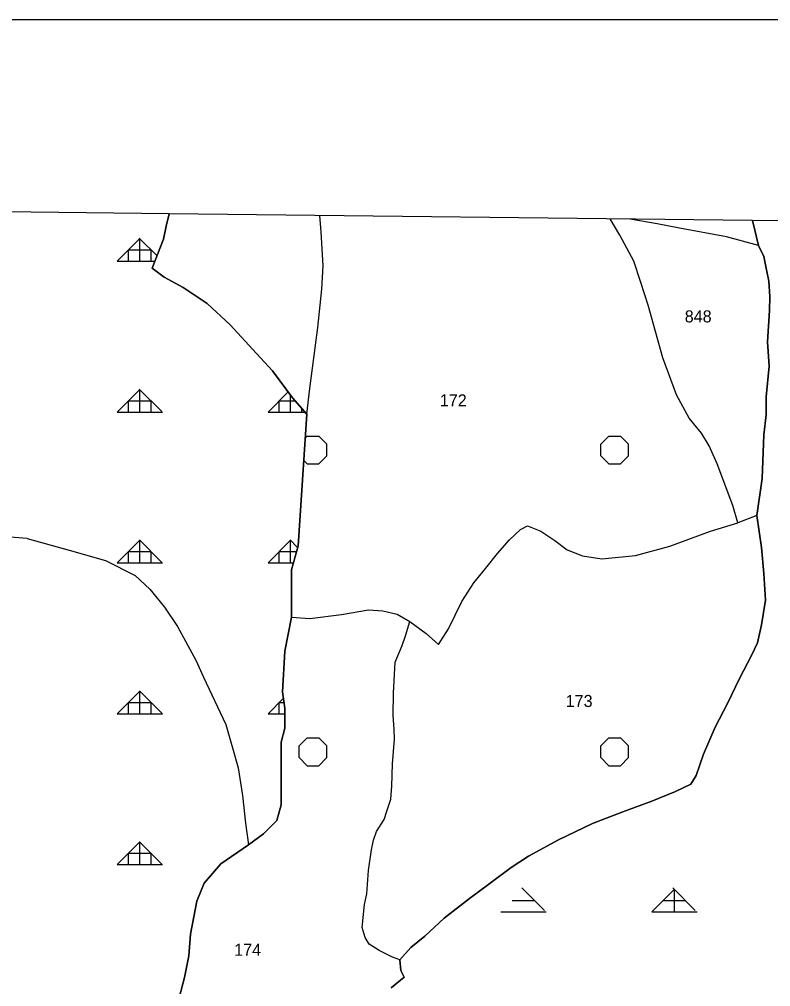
# Model space of a CAD drawing. Extents: x 410727 to 412947, y 4463506 to 4466382.
# Drawn here: x 411945.5 to 412194.6, y 4466061 to 4466381.6 of the extents above; entities that cross this region are included whole.
import ezdxf

# ---------------------------------------------------------------- set-up
doc = ezdxf.new("R2010")
doc.units = 0
for name, color, linetype in [('ADAKENARI', 7, 'Continuous'), ('KDS_PARSEL_NO', 7, 'Continuous'), ('KDS_PL', 7, 'Continuous'), ('LJ_ÇERÇEVE', 7, 'Continuous'), ('PL_AYA_ORMAN', 7, 'Continuous'), ('PL_KA_TARIM_DIGER', 7, 'Continuous'), ('TR_ORMAN', 7, 'Continuous'), ('TR_TARIMALANI', 7, 'Continuous')]:
    doc.layers.add(name, color=color, linetype=linetype)

msp = doc.modelspace()

# ---------------------------------------------------------------- linework, layer by layer
at = {"layer": 'ADAKENARI'}
for p, q in [((411995.18, 4466317.19), (411994.2, 4466313.01)), ((412188.64, 4466314.49), (412188.49, 4466314.92)), ((412190.58, 4466306.63), (412188.64, 4466314.49)), ((411994.2, 4466313.01), (411993.35, 4466308.76)), ((411993.35, 4466308.76), (411989.59, 4466299.17)), ((412192.36, 4466303.06), (412190.58, 4466306.63)), ((412193.19, 4466298.54), (412192.36, 4466303.06)), ((411989.59, 4466299.17), (411993.47, 4466296.14)), ((412194.03, 4466294.85), (412193.19, 4466298.54)), ((411993.47, 4466296.14), (411999.78, 4466292.74)), ((412194.3, 4466289.77), (412194.03, 4466294.85)), ((411999.78, 4466292.74), (412007.79, 4466287.39)), ((412194.23, 4466285.11), (412194.3, 4466289.77)), ((412007.79, 4466287.39), (412015.43, 4466280.35)), ((412193.54, 4466274.67), (412194.23, 4466285.11)), ((412015.43, 4466280.35), (412024.17, 4466270.89)), ((412194.1, 4466266.67), (412193.54, 4466274.67)), ((412024.17, 4466270.89), (412029.39, 4466265.07)), ((412193.12, 4466256.51), (412194.1, 4466266.67)), ((412029.39, 4466265.07), (412036.06, 4466256.21)), ((412036.06, 4466256.21), (412040.79, 4466250.75)), ((412193.12, 4466250.53), (412193.12, 4466256.51)), ((412040.79, 4466250.75), (412037.93, 4466207.15)), ((412040.79, 4466250.75), (412040.79, 4466250.75)), ((412192.29, 4466243.92), (412193.12, 4466250.53)), ((412191.73, 4466229.38), (412192.29, 4466243.92)), ((412189.99, 4466217.14), (412191.73, 4466229.38)), ((412191.58, 4466206.6), (412189.99, 4466217.14)), ((412037.93, 4466207.15), (412035.73, 4466199.13)), ((412192.29, 4466198), (412191.58, 4466206.6)), ((412035.73, 4466199.13), (412035.73, 4466183.47)), ((412192.85, 4466189.11), (412192.29, 4466198)), ((412191.58, 4466180.93), (412192.85, 4466189.11)), ((412035.73, 4466183.47), (412033.48, 4466172.18)), ((412190.17, 4466175), (412191.58, 4466180.93)), ((412188.27, 4466170.77), (412190.17, 4466175)), ((412033.48, 4466172.18), (412032.79, 4466158.71)), ((412184.26, 4466163.15), (412188.27, 4466170.77)), ((412180.24, 4466154.83), (412184.26, 4466163.15)), ((412032.79, 4466158.71), (412033.53, 4466153.32)), ((412176.23, 4466147.07), (412180.24, 4466154.83)), ((412033.53, 4466153.32), (412033.53, 4466146.71)), ((412033.53, 4466146.71), (412032.3, 4466142.05)), ((412172.36, 4466138.06), (412176.23, 4466147.07)), ((412032.3, 4466142.05), (412032.3, 4466137.15)), ((412169.87, 4466131), (412172.36, 4466138.06)), ((412032.3, 4466137.15), (412032.3, 4466133.48)), ((412032.3, 4466133.48), (412032.3, 4466128.58)), ((412032.3, 4466128.58), (412032.3, 4466121.23)), ((412163.09, 4466125.73), (412168.07, 4466128.08)), ((412168.07, 4466128.08), (412169.87, 4466131)), ((412155.21, 4466122.54), (412163.09, 4466125.73)), ((412145.53, 4466118.94), (412155.21, 4466122.54)), ((412032.3, 4466121.23), (412030.84, 4466116.08)), ((412135.57, 4466115.06), (412145.53, 4466118.94)), ((412030.84, 4466116.08), (412026.43, 4466111.67)), ((412124.23, 4466109.65), (412135.57, 4466115.06)), ((412026.43, 4466111.67), (412021.48, 4466107.99)), ((412114.27, 4466104.25), (412124.23, 4466109.65)), ((412021.48, 4466107.99), (412012.31, 4466101.72)), ((412108.6, 4466100.5), (412114.27, 4466104.25)), ((412012.31, 4466101.72), (412006.79, 4466095.33)), ((412101.13, 4466094.96), (412108.6, 4466100.5)), ((412006.79, 4466095.33), (412004.32, 4466089.32)), ((412094.76, 4466090.25), (412101.13, 4466094.96)), ((412086.33, 4466083.74), (412094.76, 4466090.25)), ((412004.32, 4466089.32), (412002.22, 4466078.45)), ((412079.96, 4466077.78), (412086.33, 4466083.74)), ((412002.22, 4466078.45), (412001.67, 4466071.26)), ((412075.26, 4466074.03), (412079.96, 4466077.78)), ((412071.66, 4466069.88), (412075.26, 4466074.03)), ((412001.67, 4466071.26), (412000.29, 4466064.06)), ((412071.94, 4466066.41), (412071.66, 4466069.88)), ((412000.29, 4466064.06), (411997.25, 4466052.69)), ((412068.76, 4466060.59), (412073.05, 4466064.19)), ((412073.05, 4466064.19), (412071.94, 4466066.41))]:
    msp.add_line(p, q, dxfattribs=at)
at = {"layer": 'KDS_PL'}
for p, q in [((411995.18, 4466317.19), (411994.2, 4466313.01)), ((412045.53, 4466311.18), (412045.13, 4466316.6)), ((412144.59, 4466310.02), (412141.35, 4466315.48)), ((412156.99, 4466313.79), (412148.01, 4466315.4)), ((412188.49, 4466314.92), (412188.64, 4466314.49)), ((412188.64, 4466314.49), (412190.58, 4466306.63)), ((411994.2, 4466313.01), (411993.35, 4466308.76)), ((412046.26, 4466299.9), (412045.53, 4466311.18)), ((412164.36, 4466312.4), (412156.99, 4466313.79)), ((412179.94, 4466309.48), (412164.36, 4466312.4)), ((411993.35, 4466308.76), (411989.59, 4466299.17)), ((412149.26, 4466301.46), (412144.59, 4466310.02)), ((412190.58, 4466306.63), (412179.94, 4466309.48)), ((412190.58, 4466306.63), (412192.36, 4466303.06)), ((412151.55, 4466294.36), (412149.26, 4466301.46)), ((412192.36, 4466303.06), (412193.19, 4466298.54)), ((411989.59, 4466299.17), (411993.47, 4466296.14)), ((412045.77, 4466292.13), (412046.26, 4466299.9)), ((412193.19, 4466298.54), (412194.03, 4466294.85)), ((411993.47, 4466296.14), (411999.78, 4466292.74)), ((412194.03, 4466294.85), (412194.3, 4466289.77)), ((411999.78, 4466292.74), (412007.79, 4466287.39)), ((412044.43, 4466279.51), (412045.77, 4466292.13)), ((412153.99, 4466286.85), (412151.55, 4466294.36)), ((412194.3, 4466289.77), (412194.23, 4466285.11)), ((412007.79, 4466287.39), (412015.43, 4466280.35)), ((412156.42, 4466278.15), (412153.99, 4466286.85)), ((412194.23, 4466285.11), (412193.54, 4466274.67)), ((412015.43, 4466280.35), (412024.17, 4466270.89)), ((412041.77, 4466259.24), (412044.43, 4466279.51)), ((412158.79, 4466269.45), (412156.42, 4466278.15)), ((412193.54, 4466274.67), (412194.1, 4466266.67)), ((412024.17, 4466270.89), (412029.39, 4466265.07)), ((412163.38, 4466257.14), (412158.79, 4466269.45)), ((412194.1, 4466266.67), (412193.12, 4466256.51)), ((412029.39, 4466265.07), (412036.06, 4466256.21)), ((412036.06, 4466256.21), (412040.79, 4466250.75)), ((412040.79, 4466250.75), (412041.77, 4466259.24)), ((412167.55, 4466249.48), (412163.38, 4466257.14)), ((412193.12, 4466256.51), (412193.12, 4466250.53)), ((412040.79, 4466250.75), (412037.93, 4466207.15)), ((412193.12, 4466250.53), (412192.29, 4466243.92)), ((412171.66, 4466244.47), (412167.55, 4466249.48)), ((412174.17, 4466240.23), (412171.66, 4466244.47)), ((412192.29, 4466243.92), (412191.73, 4466229.38)), ((412176.88, 4466234.25), (412174.17, 4466240.23)), ((412182.1, 4466220.46), (412176.88, 4466234.25)), ((412191.73, 4466229.38), (412189.99, 4466217.14)), ((412183.7, 4466214.76), (412182.1, 4466220.46)), ((412174.69, 4466211.96), (412183.7, 4466214.76)), ((412189.99, 4466217.14), (412183.7, 4466214.76)), ((412189.99, 4466217.14), (412191.58, 4466206.6)), ((412107.96, 4466209.14), (412111.62, 4466212.53)), ((412111.62, 4466212.53), (412114.01, 4466213.8)), ((412114.01, 4466213.8), (412118.37, 4466211.96)), ((412118.37, 4466211.96), (412123.02, 4466208.86)), ((412161.17, 4466207.02), (412174.69, 4466211.96)), ((411948.06, 4466209.59), (411932.84, 4466210.69)), ((411948.06, 4466209.59), (411961.99, 4466205.69)), ((412104.02, 4466204.63), (412107.96, 4466209.14)), ((412123.02, 4466208.86), (412127.1, 4466205.75)), ((411961.99, 4466205.69), (411974.07, 4466202.26)), ((412035.73, 4466199.13), (412037.93, 4466207.15)), ((412127.1, 4466205.75), (412132.17, 4466203.78)), ((412149.77, 4466203.92), (412161.17, 4466207.02)), ((412191.58, 4466206.6), (412192.29, 4466198)), ((411974.07, 4466202.26), (411983.87, 4466197.24)), ((412100.21, 4466199.69), (412104.02, 4466204.63)), ((412132.17, 4466203.78), (412138.65, 4466202.79)), ((412138.65, 4466202.79), (412149.77, 4466203.92)), ((412035.73, 4466183.47), (412035.73, 4466199.13)), ((412096.13, 4466194.89), (412100.21, 4466199.69)), ((411983.87, 4466197.24), (411988.72, 4466192.77)), ((412192.29, 4466198), (412192.85, 4466189.11)), ((411988.72, 4466192.77), (411993.66, 4466186.74)), ((412092.19, 4466188.69), (412096.13, 4466194.89)), ((412192.85, 4466189.11), (412191.58, 4466180.93)), ((411993.66, 4466186.74), (411997.99, 4466180.43)), ((412052.35, 4466184.31), (412061.22, 4466185.87)), ((412061.22, 4466185.87), (412066, 4466185.58)), ((412087.82, 4466179.66), (412092.19, 4466188.69)), ((412033.48, 4466172.18), (412035.73, 4466183.47)), ((412035.73, 4466183.47), (412041.79, 4466183.04)), ((412041.79, 4466183.04), (412052.35, 4466184.31)), ((412066, 4466185.58), (412070.79, 4466184.46)), ((412070.79, 4466184.46), (412075.01, 4466182.06)), ((411997.99, 4466180.43), (412004.02, 4466169.24)), ((412073.49, 4466177.28), (412075.01, 4466182.06)), ((412075.01, 4466182.06), (412080.36, 4466178.11)), ((412084.45, 4466174.44), (412087.82, 4466179.66)), ((412191.58, 4466180.93), (412190.17, 4466175)), ((412072.39, 4466174.1), (412073.49, 4466177.28)), ((412080.36, 4466178.11), (412084.45, 4466174.44)), ((412070.13, 4466168.59), (412072.39, 4466174.1)), ((412188.27, 4466170.77), (412190.17, 4466175)), ((412032.79, 4466158.71), (412033.48, 4466172.18)), ((412184.26, 4466163.15), (412188.27, 4466170.77)), ((412004.02, 4466169.24), (412006.52, 4466163.54)), ((412069.52, 4466158.32), (412070.13, 4466168.59)), ((412006.52, 4466163.54), (412013.97, 4466147.94)), ((412180.24, 4466154.83), (412184.26, 4466163.15)), ((412033.53, 4466153.32), (412032.79, 4466158.71)), ((412069.46, 4466150.85), (412069.52, 4466158.32)), ((412176.23, 4466147.07), (412180.24, 4466154.83)), ((412033.53, 4466146.71), (412033.53, 4466153.32)), ((412069.82, 4466146.39), (412069.46, 4466150.85)), ((412013.97, 4466147.94), (412016.2, 4466140.14)), ((412032.3, 4466142.05), (412033.53, 4466146.71)), ((412069.88, 4466143.02), (412069.82, 4466146.39)), ((412172.36, 4466138.06), (412176.23, 4466147.07)), ((412032.3, 4466137.15), (412032.3, 4466142.05)), ((412069.21, 4466134.83), (412069.88, 4466143.02)), ((412016.2, 4466140.14), (412018.1, 4466133.56)), ((412169.87, 4466131), (412172.36, 4466138.06)), ((412032.3, 4466133.48), (412032.3, 4466137.15)), ((412069.03, 4466127.42), (412069.21, 4466134.83)), ((412018.1, 4466133.56), (412019.45, 4466124.33)), ((412032.3, 4466128.58), (412032.3, 4466133.48)), ((412032.3, 4466121.23), (412032.3, 4466128.58)), ((412163.09, 4466125.73), (412168.07, 4466128.08)), ((412168.07, 4466128.08), (412169.87, 4466131)), ((412068.66, 4466123.2), (412069.03, 4466127.42)), ((412155.21, 4466122.54), (412163.09, 4466125.73)), ((412019.45, 4466124.33), (412020.53, 4466115.18)), ((412067.38, 4466119.16), (412068.66, 4466123.2)), ((412145.53, 4466118.94), (412155.21, 4466122.54)), ((412030.84, 4466116.08), (412032.3, 4466121.23)), ((412066.41, 4466116.41), (412067.38, 4466119.16)), ((412135.57, 4466115.06), (412145.53, 4466118.94)), ((412020.53, 4466115.18), (412021.48, 4466107.99)), ((412026.43, 4466111.67), (412030.84, 4466116.08)), ((412063.9, 4466112.43), (412066.41, 4466116.41)), ((412062.92, 4466109.56), (412063.9, 4466112.43)), ((412124.23, 4466109.65), (412135.57, 4466115.06)), ((412021.48, 4466107.99), (412026.43, 4466111.67)), ((412062.25, 4466106.32), (412062.92, 4466109.56)), ((412114.27, 4466104.25), (412124.23, 4466109.65)), ((412021.48, 4466107.99), (412012.31, 4466101.72)), ((412061.21, 4466099.53), (412062.25, 4466106.32)), ((412108.6, 4466100.5), (412114.27, 4466104.25)), ((412012.31, 4466101.72), (412006.79, 4466095.33)), ((412060.67, 4466091.82), (412061.21, 4466099.53)), ((412101.13, 4466094.96), (412108.6, 4466100.5)), ((412006.79, 4466095.33), (412004.32, 4466089.32)), ((412094.76, 4466090.25), (412101.13, 4466094.96)), ((412059.99, 4466088.21), (412060.67, 4466091.82)), ((412086.33, 4466083.74), (412094.76, 4466090.25)), ((412004.32, 4466089.32), (412002.22, 4466078.45)), ((412059.14, 4466080.62), (412059.99, 4466088.21)), ((412079.96, 4466077.78), (412086.33, 4466083.74)), ((412060.18, 4466077.32), (412059.14, 4466080.62)), ((412002.22, 4466078.45), (412001.67, 4466071.26)), ((412061.52, 4466075.12), (412060.18, 4466077.32)), ((412075.26, 4466074.03), (412079.96, 4466077.78)), ((412064.76, 4466072.97), (412061.52, 4466075.12)), ((412071.66, 4466069.88), (412075.26, 4466074.03)), ((412001.67, 4466071.26), (412000.29, 4466064.06)), ((412069.21, 4466070.77), (412064.76, 4466072.97)), ((412071.66, 4466069.88), (412069.21, 4466070.77)), ((412071.94, 4466066.41), (412071.66, 4466069.88)), ((412000.29, 4466064.06), (411997.25, 4466052.69)), ((412068.76, 4466060.59), (412073.05, 4466064.19)), ((412073.05, 4466064.19), (412071.94, 4466066.41))]:
    msp.add_line(p, q, dxfattribs=at)
at = {"layer": 'LJ_ÇERÇEVE'}
msp.add_lwpolyline([(410732.32, 4466381.6), (412946.74, 4466381.6), (412946.74, 4463506.16), (410732.32, 4463506.16)], close=True, dxfattribs=at)
at = {"layer": 'PL_AYA_ORMAN'}
for points in [[(411995.18, 4466317.19), (411912.75, 4466318.15)], [(411997.25, 4466052.69), (412000.29, 4466064.06), (412001.67, 4466071.26), (412002.22, 4466078.45), (412004.32, 4466089.32), (412006.79, 4466095.33), (412012.31, 4466101.72), (412021.48, 4466107.99), (412026.43, 4466111.67), (412030.84, 4466116.08), (412032.3, 4466121.23), (412032.3, 4466128.58), (412032.3, 4466133.48), (412032.3, 4466137.15), (412032.3, 4466142.05), (412033.53, 4466146.71), (412033.53, 4466153.32), (412032.79, 4466158.71), (412033.48, 4466172.18), (412035.73, 4466183.47), (412035.73, 4466199.13), (412037.93, 4466207.15), (412040.79, 4466250.75), (412036.06, 4466256.21), (412029.39, 4466265.07), (412024.17, 4466270.89), (412015.43, 4466280.35), (412007.79, 4466287.39), (411999.78, 4466292.74), (411993.47, 4466296.14), (411989.59, 4466299.17), (411993.35, 4466308.76), (411994.2, 4466313.01), (411995.18, 4466317.19)], [(412922.18, 4466306.32), (412188.49, 4466314.92), (412188.64, 4466314.49), (412190.58, 4466306.63), (412192.36, 4466303.06), (412193.19, 4466298.54), (412194.03, 4466294.85), (412194.3, 4466289.77), (412194.23, 4466285.11), (412193.54, 4466274.67), (412194.1, 4466266.67), (412193.12, 4466256.51), (412193.12, 4466250.53), (412192.29, 4466243.92), (412191.73, 4466229.38), (412189.99, 4466217.14), (412191.58, 4466206.6), (412192.29, 4466198), (412192.85, 4466189.11), (412191.58, 4466180.93), (412190.17, 4466175), (412188.27, 4466170.77), (412184.26, 4466163.15), (412180.24, 4466154.83), (412176.23, 4466147.07), (412172.36, 4466138.06), (412169.87, 4466131), (412168.07, 4466128.08), (412163.09, 4466125.73), (412155.21, 4466122.54), (412145.53, 4466118.94), (412135.57, 4466115.06), (412124.23, 4466109.65), (412114.27, 4466104.25), (412108.6, 4466100.5), (412101.13, 4466094.96), (412094.76, 4466090.25), (412086.33, 4466083.74), (412079.96, 4466077.78), (412075.26, 4466074.03), (412071.66, 4466069.88), (412071.94, 4466066.41), (412073.05, 4466064.19), (412068.76, 4466060.59)]]:
    msp.add_lwpolyline(points, dxfattribs=at)
at = {"layer": 'PL_KA_TARIM_DIGER'}
for points in [[(412188.49, 4466314.92), (411995.18, 4466317.19), (411994.2, 4466313.01), (411993.35, 4466308.76), (411989.59, 4466299.17), (411993.47, 4466296.14), (411999.78, 4466292.74), (412007.79, 4466287.39), (412015.43, 4466280.35), (412024.17, 4466270.89), (412029.39, 4466265.07), (412036.06, 4466256.21), (412040.79, 4466250.75), (412037.93, 4466207.15), (412035.73, 4466199.13), (412035.73, 4466183.47), (412033.48, 4466172.18), (412032.79, 4466158.71), (412033.53, 4466153.32), (412033.53, 4466146.71), (412032.3, 4466142.05), (412032.3, 4466137.15), (412032.3, 4466133.48), (412032.3, 4466128.58), (412032.3, 4466121.23), (412030.84, 4466116.08), (412026.43, 4466111.67), (412021.48, 4466107.99), (412012.31, 4466101.72), (412006.79, 4466095.33), (412004.32, 4466089.32), (412002.22, 4466078.45), (412001.67, 4466071.26), (412000.29, 4466064.06), (411997.25, 4466052.69)], [(412068.76, 4466060.59), (412073.05, 4466064.19), (412071.94, 4466066.41), (412071.66, 4466069.88), (412075.26, 4466074.03), (412079.96, 4466077.78), (412086.33, 4466083.74), (412094.76, 4466090.25), (412101.13, 4466094.96), (412108.6, 4466100.5), (412114.27, 4466104.25), (412124.23, 4466109.65), (412135.57, 4466115.06), (412145.53, 4466118.94), (412155.21, 4466122.54), (412163.09, 4466125.73), (412168.07, 4466128.08), (412169.87, 4466131), (412172.36, 4466138.06), (412176.23, 4466147.07), (412180.24, 4466154.83), (412184.26, 4466163.15), (412188.27, 4466170.77), (412190.17, 4466175), (412191.58, 4466180.93), (412192.85, 4466189.11), (412192.29, 4466198), (412191.58, 4466206.6), (412189.99, 4466217.14), (412191.73, 4466229.38), (412192.29, 4466243.92), (412193.12, 4466250.53), (412193.12, 4466256.51), (412194.1, 4466266.67), (412193.54, 4466274.67), (412194.23, 4466285.11), (412194.3, 4466289.77), (412194.03, 4466294.85), (412193.19, 4466298.54), (412192.36, 4466303.06), (412190.58, 4466306.63), (412188.64, 4466314.49), (412188.49, 4466314.92)]]:
    msp.add_lwpolyline(points, dxfattribs=at)
at = {"layer": 'TR_ORMAN'}
for p, q in [((411977.95, 4466301.45), (411985.45, 4466308.95)), ((411991.16, 4466303.18), (411985.23, 4466309.11)), ((411985.45, 4466301.47), (411985.45, 4466308.97)), ((411981.7, 4466301.47), (411981.7, 4466305.22)), ((411981.7, 4466305.22), (411989.2, 4466305.22)), ((411989.2, 4466301.47), (411989.2, 4466305.22)), ((411977.95, 4466301.47), (411990.49, 4466301.47)), ((411977.95, 4466251.46), (411985.45, 4466258.96)), ((411992.76, 4466251.59), (411985.26, 4466259.09)), ((411985.45, 4466251.47), (411985.45, 4466258.97)), ((412027.95, 4466251.47), (412034.61, 4466258.13)), ((412035.45, 4466251.47), (412035.45, 4466257.02)), ((411981.7, 4466255.22), (411989.2, 4466255.22)), ((411981.7, 4466251.47), (411981.7, 4466255.22)), ((411989.2, 4466251.47), (411989.2, 4466255.22)), ((412031.7, 4466251.47), (412031.7, 4466255.22)), ((412031.7, 4466255.22), (412036.92, 4466255.22)), ((411977.95, 4466251.47), (411992.95, 4466251.47)), ((412027.95, 4466251.47), (412040.17, 4466251.47)), ((412039.2, 4466251.47), (412039.2, 4466252.58)), ((411977.95, 4466201.47), (411985.45, 4466208.96)), ((411992.79, 4466201.57), (411985.29, 4466209.06)), ((411985.45, 4466201.47), (411985.45, 4466208.97)), ((412027.95, 4466201.47), (412035.45, 4466208.97)), ((412037.77, 4466206.58), (412035.29, 4466209.06)), ((412035.45, 4466201.47), (412035.45, 4466208.97)), ((411981.7, 4466205.22), (411989.2, 4466205.22)), ((411981.7, 4466201.47), (411981.7, 4466205.22)), ((411989.2, 4466201.47), (411989.2, 4466205.22)), ((412031.7, 4466201.47), (412031.7, 4466205.22)), ((412031.7, 4466205.22), (412037.4, 4466205.22)), ((411977.95, 4466201.47), (411992.95, 4466201.47)), ((412027.95, 4466201.47), (412036.37, 4466201.47)), ((411977.95, 4466151.47), (411985.45, 4466158.97)), ((411992.83, 4466151.54), (411985.33, 4466159.04)), ((411985.45, 4466151.47), (411985.45, 4466158.97)), ((411981.7, 4466155.22), (411989.2, 4466155.22)), ((411981.7, 4466151.47), (411981.7, 4466155.22)), ((411989.2, 4466151.47), (411989.2, 4466155.22)), ((412027.95, 4466151.48), (412033.08, 4466156.61)), ((412031.7, 4466151.47), (412031.7, 4466155.22)), ((412031.7, 4466155.22), (412033.27, 4466155.22)), ((411977.95, 4466151.47), (411992.95, 4466151.47)), ((412027.95, 4466151.47), (412033.53, 4466151.47)), ((411977.95, 4466101.48), (411985.45, 4466108.98)), ((411992.86, 4466101.52), (411985.36, 4466109.02)), ((411985.45, 4466101.47), (411985.45, 4466108.97)), ((411981.7, 4466101.47), (411981.7, 4466105.22)), ((411981.7, 4466105.22), (411989.2, 4466105.22)), ((411989.2, 4466101.47), (411989.2, 4466105.22)), ((411977.95, 4466101.47), (411992.95, 4466101.47)), ((412119.61, 4466086.23), (412112.12, 4466093.72)), ((412119.61, 4466086.23), (412112.12, 4466093.72)), ((412155.16, 4466085.83), (412162.66, 4466093.32)), ((412155.16, 4466085.83), (412162.66, 4466093.32)), ((412169.61, 4466086.23), (412162.11, 4466093.72)), ((412169.61, 4466086.23), (412162.11, 4466093.72)), ((412162.67, 4466085.86), (412162.67, 4466093.36)), ((412108.92, 4466089.61), (412116.42, 4466089.61)), ((412158.92, 4466089.61), (412166.42, 4466089.61)), ((412105.17, 4466085.86), (412120.17, 4466085.86)), ((412155.17, 4466085.86), (412170.17, 4466085.86))]:
    msp.add_line(p, q, dxfattribs=at)
at = {"layer": 'TR_TARIMALANI'}
for p, q in [((412040.27, 4466242.82), (412040.95, 4466243.5)), ((412040.96, 4466243.51), (412044.79, 4466243.51)), ((412047.49, 4466240.8), (412044.79, 4466243.5)), ((412138.24, 4466240.8), (412140.95, 4466243.5)), ((412140.96, 4466243.51), (412144.79, 4466243.51)), ((412147.49, 4466240.8), (412144.79, 4466243.5)), ((412047.5, 4466236.97), (412047.5, 4466240.8)), ((412138.25, 4466236.97), (412138.25, 4466240.8)), ((412147.5, 4466236.97), (412147.5, 4466240.8)), ((412044.78, 4466234.26), (412047.49, 4466236.96)), ((412140.95, 4466234.26), (412138.25, 4466236.96)), ((412144.78, 4466234.26), (412147.49, 4466236.96)), ((412040.95, 4466234.26), (412039.79, 4466235.42)), ((412040.96, 4466234.26), (412044.79, 4466234.26)), ((412140.96, 4466234.26), (412144.79, 4466234.26)), ((412038.24, 4466140.8), (412040.95, 4466143.5)), ((412038.25, 4466136.97), (412038.25, 4466140.8)), ((412040.96, 4466143.51), (412044.79, 4466143.51)), ((412040.96, 4466143.51), (412044.79, 4466143.51)), ((412047.49, 4466140.8), (412044.79, 4466143.5)), ((412047.5, 4466136.97), (412047.5, 4466140.8)), ((412138.24, 4466140.8), (412140.95, 4466143.5)), ((412138.25, 4466136.97), (412138.25, 4466140.8)), ((412140.96, 4466143.51), (412144.79, 4466143.51)), ((412140.96, 4466143.51), (412144.79, 4466143.51)), ((412147.49, 4466140.8), (412144.79, 4466143.5)), ((412147.5, 4466136.97), (412147.5, 4466140.8)), ((412040.95, 4466134.26), (412038.25, 4466136.96)), ((412044.78, 4466134.26), (412047.49, 4466136.96)), ((412140.95, 4466134.26), (412138.25, 4466136.96)), ((412144.78, 4466134.26), (412147.49, 4466136.96)), ((412040.96, 4466134.26), (412044.79, 4466134.26)), ((412140.96, 4466134.26), (412144.79, 4466134.26))]:
    msp.add_line(p, q, dxfattribs=at)

# ---------------------------------------------------------------- texts
at = {"layer": 'KDS_PARSEL_NO'}
for s, p in [('848', (412166.1, 4466281.16)), ('172', (412084.9, 4466253.31)), ('173', (412126.63, 4466153.7)), ('174', (412016.72, 4466071.24))]:
    msp.add_text(s, height=4, dxfattribs=at).set_placement(p)

doc.saveas('drawing.dxf')
